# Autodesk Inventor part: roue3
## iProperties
Author: Administrateur
Shininess: 20.0
PropertySet Name: _Private Model Information
Length Units: 11269
Angle Units: 11283
Time Units: 11279
Mass Units: 11290
Length Display Precision: 3
Angle Display Precision: 2
Compacted: False
Created: 2001-04
Part Number: roue3
Material: Par défaut
Document SubType Name: Modélisation
Designer: Administrateur
Control State: 0
Master: False
Checked Out: False
PropertySet Name: Design Tracking Control
Density: 0.0
Volumn: 0.0
Area: 0.0
PropertySet Name: Model Information
